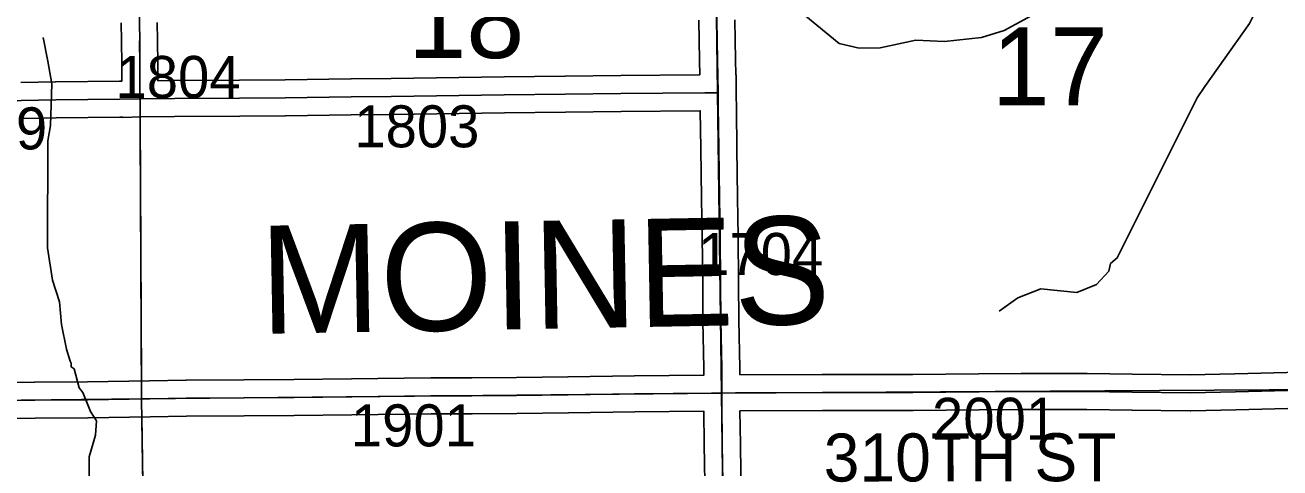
# Model space of a CAD drawing. Extents: x 23.6 to 68.7, y -63 to -29.
# Drawn here: x 38.618 to 40.707, y -54.804 to -54.066 of the extents above; entities that cross this region are included whole.
import ezdxf

# ---------------------------------------------------------------- set-up
doc = ezdxf.new("R2010")
doc.units = 0
for name, color, linetype in [('tdCoHydroRiver', 7, 'Continuous'), ('tdCoSecRdNmbr', 7, 'Continuous'), ('tdCoSecRdTxt', 7, 'Continuous'), ('tdCoSecRteBand', 7, 'Continuous'), ('tdCoSecRteCL', 7, 'Continuous'), ('tdCoSectLine', 7, 'Continuous'), ('tdCoSectLinePart', 7, 'Continuous'), ('tdCoSectNmbr', 7, 'Continuous'), ('tdCoSurfAsphalt', 7, 'Continuous'), ('tdCoSurfGravel', 7, 'Continuous'), ('tdCoTwpBndry', 7, 'Continuous'), ('tdCoTwpBndryShd', 7, 'Continuous'), ('tdCoTwpNameTxt', 7, 'Continuous')]:
    doc.layers.add(name, color=color, linetype=linetype)

msp = doc.modelspace()

# ---------------------------------------------------------------- linework, layer by layer
at = {"layer": 'tdCoHydroRiver'}
for points in [[(40.7641, -53.759), (40.6872, -53.7992), (40.6525, -53.8043), (40.6098, -53.7952), (40.5829, -53.7923), (40.5704, -53.8003), (40.4953, -53.8768), (40.4265, -53.9485), (40.3748, -53.9821), (40.3467, -54.0187), (40.3059, -54.0428), (40.2478, -54.0749), (40.21, -54.0863), (40.1485, -54.0932), (40.1011, -54.0905), (40.0413, -54.1037), (40.0065, -54.104), (39.9733, -54.0965), (39.9144, -54.0481), (39.9049, -54.0434), (39.8796, -54.0405), (39.8639, -54.0454)], [(41, -53.8247), (40.9937, -53.8279), (40.98, -53.8801), (40.966, -53.9007), (40.9424, -53.912), (40.9202, -53.9043), (40.9012, -53.9029), (40.8417, -53.9446), (40.7741, -53.9784), (40.7158, -53.9915), (40.6796, -54.0045), (40.6687, -54.0172), (40.6658, -54.0441), (40.6565, -54.0631), (40.5817, -54.168), (40.5693, -54.1871), (40.4361, -54.4536), (40.4251, -54.4631), (40.4221, -54.4758), (40.4018, -54.4981), (40.3687, -54.511), (40.3087, -54.5053), (40.2709, -54.5199), (40.2396, -54.5423)], [(38.7382, -55.107), (38.734, -54.9807), (38.7307, -54.965), (38.7254, -54.8893), (38.7245, -54.7851), (38.7353, -54.7487), (38.7367, -54.725), (38.7271, -54.7093), (38.7142, -54.6778), (38.7078, -54.67), (38.6997, -54.6385), (38.6949, -54.6353), (38.6948, -54.629), (38.6932, -54.6259), (38.6868, -54.6054), (38.6785, -54.5644), (38.6751, -54.5266), (38.6637, -54.4904), (38.6554, -54.4368), (38.6556, -54.2584), (38.6601, -54.2331), (38.6627, -54.1636), (38.6561, -54.1258), (38.6479, -54.0864)]]:
    msp.add_lwpolyline(points, dxfattribs=at)
at = {"layer": 'tdCoSecRteBand'}
for points in [[(38.838, -54.0612), (38.8384, -54.0912), (38.839, -54.1302), (38.839, -54.1303), (38.839, -54.1304), (38.8392, -54.1583), (38.8394, -54.1583), (38.8394, -54.1584), (38.8663, -54.1582), (38.975, -54.1572), (38.975, -54.1572), (38.9751, -54.1572), (39.0507, -54.1569), (39.1602, -54.1552), (39.1603, -54.1552), (39.1603, -54.1552), (39.2272, -54.1544), (39.4154, -54.1521), (39.5168, -54.1506), (39.5169, -54.1506), (39.517, -54.1506), (39.6097, -54.1498), (39.7412, -54.1484), (39.7408, -54.1245), (39.7408, -54.1245), (39.7408, -54.1245), (39.7398, -54.0576)], [(39.7998, -54.0567), (39.8008, -54.1235), (39.8012, -54.1479), (39.8012, -54.1483), (39.8016, -54.1483), (39.8016, -54.1781), (39.8021, -54.2078), (39.8021, -54.2078), (39.803, -54.2706), (39.803, -54.2706), (39.803, -54.2706), (39.804, -54.3537), (39.805, -54.418), (39.805, -54.418), (39.805, -54.4181), (39.8059, -54.4933), (39.8059, -54.4934), (39.8059, -54.4934), (39.8064, -54.5579), (39.8079, -54.6366), (39.8079, -54.6369), (39.8079, -54.6372), (39.8079, -54.6486)], [(38.611, -54.1612), (38.6689, -54.1602), (38.669, -54.1602), (38.6691, -54.1602), (38.7753, -54.1589), (38.7754, -54.1589), (38.7754, -54.1589), (38.7792, -54.1589), (38.779, -54.1309), (38.7784, -54.092), (38.7781, -54.062)], [(38.5547, -54.662), (38.6337, -54.6607), (38.6339, -54.6606), (38.634, -54.6606), (38.7221, -54.66), (38.8252, -54.6582), (38.8252, -54.6582), (38.8253, -54.6582), (38.8858, -54.6573), (38.886, -54.6573), (38.8861, -54.6573), (38.9823, -54.6569), (39.0655, -54.656), (39.1614, -54.6549), (39.1614, -54.6549), (39.1614, -54.6549), (39.2934, -54.6536), (39.2935, -54.6536), (39.2936, -54.6536), (39.3616, -54.6534), (39.4359, -54.6528), (39.5218, -54.6515), (39.5218, -54.6515), (39.5219, -54.6515), (39.6323, -54.6501), (39.6324, -54.6501), (39.6324, -54.6501), (39.7479, -54.6492), (39.7479, -54.6489), (39.7479, -54.6375), (39.7464, -54.5588), (39.7464, -54.5587), (39.7464, -54.5585), (39.746, -54.494), (39.745, -54.4189), (39.744, -54.3546), (39.744, -54.3545), (39.744, -54.3544), (39.743, -54.2714), (39.7421, -54.2084), (39.6103, -54.2098), (39.6103, -54.2098), (39.6103, -54.2098), (39.5176, -54.2106), (39.4163, -54.2121), (39.4162, -54.2121), (39.4162, -54.2121), (39.228, -54.2144), (39.1611, -54.2152), (39.0515, -54.2169), (39.0513, -54.2169), (39.0512, -54.2169), (38.9754, -54.2172), (38.8668, -54.2182), (38.8667, -54.2182), (38.8667, -54.2182), (38.8102, -54.2186), (38.7806, -54.2194), (38.7806, -54.2189), (38.776, -54.2189), (38.6699, -54.2202), (38.6119, -54.2212)], [(39.8079, -54.6486), (39.9452, -54.648), (39.9452, -54.648), (39.9452, -54.648), (40.0958, -54.6477), (40.2058, -54.6465), (40.2058, -54.6465), (40.2059, -54.6465), (40.2764, -54.646), (40.2765, -54.646), (40.2766, -54.646), (40.3855, -54.646), (40.3858, -54.646), (40.386, -54.646), (40.4613, -54.6471), (40.5577, -54.6483), (40.6321, -54.6465), (40.6321, -54.6465), (40.6321, -54.6465), (40.7402, -54.6441)], [(40.7416, -54.7041), (40.6335, -54.7065), (40.5586, -54.7083), (40.5581, -54.7083), (40.5575, -54.7083), (40.4605, -54.7071), (40.4605, -54.7071), (40.4605, -54.7071), (40.3853, -54.706), (40.2767, -54.706), (40.2064, -54.7065), (40.0963, -54.7077), (40.0962, -54.7077), (40.096, -54.7077), (39.9454, -54.708), (39.8081, -54.7086), (39.8087, -54.7641), (39.8099, -54.858)], [(39.7499, -54.8587), (39.7487, -54.7648), (39.7487, -54.7648), (39.7487, -54.7648), (39.7481, -54.7092), (39.633, -54.7101), (39.5227, -54.7115), (39.4367, -54.7128), (39.4366, -54.7128), (39.4365, -54.7128), (39.362, -54.7134), (39.3619, -54.7134), (39.3618, -54.7134), (39.2939, -54.7136), (39.162, -54.7149), (39.0662, -54.716), (39.0662, -54.716), (39.0662, -54.716), (38.9829, -54.7169), (38.9828, -54.7169), (38.9827, -54.7169), (38.8866, -54.7173), (38.8262, -54.7182), (38.723, -54.72), (38.7229, -54.72), (38.7227, -54.72), (38.6346, -54.7206), (38.5556, -54.722)]]:
    msp.add_lwpolyline(points, dxfattribs=at)
at = {"layer": 'tdCoSecRteCL'}
for points in [[(39.7716, -54.1783), (39.7708, -54.124), (39.7698, -54.0572), (39.769, -54.0042), (39.7681, -53.9553), (39.7678, -53.9107), (39.7668, -53.8416), (39.7661, -53.783), (39.7653, -53.7373), (39.7644, -53.6611), (39.7629, -53.5519), (39.7616, -53.468), (39.7609, -53.4015), (39.7599, -53.3243), (39.7584, -53.2333), (39.7577, -53.1752)], [(38.8097, -54.1886), (38.8093, -54.1728), (38.809, -54.1306), (38.8084, -54.0916)], [(38.8097, -54.1886), (38.8098, -54.1886), (38.8665, -54.1882), (38.9752, -54.1872), (39.051, -54.1869), (39.1607, -54.1852), (39.2276, -54.1844), (39.4158, -54.1821), (39.5173, -54.1806), (39.61, -54.1798), (39.7494, -54.1783), (39.7716, -54.1783)], [(39.7779, -54.6789), (39.7779, -54.6372), (39.7764, -54.5583), (39.7759, -54.4937), (39.775, -54.4185), (39.774, -54.3541), (39.773, -54.271), (39.772, -54.2007), (39.7716, -54.1783)], [(38.3054, -54.1933), (38.4353, -54.1935), (38.4761, -54.193), (38.6114, -54.1912), (38.6694, -54.1902), (38.7757, -54.1889), (38.8097, -54.1886)], [(37.81, -54.6998), (37.9437, -54.6985), (38.0909, -54.6974), (38.2411, -54.6953), (38.4222, -54.6932), (38.5551, -54.692), (38.6342, -54.6906), (38.7225, -54.69), (38.8257, -54.6882), (38.8863, -54.6873), (38.9826, -54.6869), (39.0659, -54.686), (39.1617, -54.6849), (39.2937, -54.6836), (39.3618, -54.6834), (39.4362, -54.6828), (39.5222, -54.6815), (39.6327, -54.6801), (39.7607, -54.679), (39.7779, -54.6789)], [(39.7779, -54.6789), (39.8005, -54.6786), (39.9453, -54.678), (40.096, -54.6777), (40.2061, -54.6765), (40.2766, -54.676), (40.3855, -54.676), (40.4609, -54.6771), (40.5579, -54.6783), (40.6328, -54.6765), (40.741, -54.6741), (40.7803, -54.6731)], [(39.7867, -55.4585), (39.7863, -55.4318), (39.7853, -55.3164), (39.7833, -55.1903), (39.7824, -55.066), (39.7809, -54.9736), (39.7799, -54.8584), (39.7787, -54.7644), (39.7779, -54.6949), (39.7779, -54.6789)]]:
    msp.add_lwpolyline(points, dxfattribs=at)
at = {"layer": 'tdCoSectLine'}
for points in [[(39.7642, -53.6757), (39.7776, -54.6788)], [(38.8068, -53.6871), (38.8119, -54.6885)], [(38.8119, -54.6885), (39.7776, -54.6788)], [(39.7776, -54.6788), (40.78, -54.6731)], [(39.7776, -54.6788), (39.79, -55.6803)], [(37.8096, -54.6998), (38.8119, -54.6885)], [(38.8119, -54.6885), (38.8276, -55.6912)]]:
    msp.add_lwpolyline(points, dxfattribs=at)
at = {"layer": 'tdCoSectLinePart'}
for points in [[(38.8095, -54.2191), (38.8118, -54.6583)], [(38.8124, -54.7183), (38.8276, -55.6912)]]:
    msp.add_lwpolyline(points, dxfattribs=at)
at = {"layer": 'tdCoSurfAsphalt'}
for points in [[(39.7779, -54.6789), (39.7779, -54.6372), (39.7764, -54.5583), (39.7759, -54.4937), (39.775, -54.4185), (39.774, -54.3541), (39.773, -54.271), (39.772, -54.2007), (39.7716, -54.1783), (39.7708, -54.124), (39.7698, -54.0572)], [(38.5551, -54.692), (38.6342, -54.6906), (38.7225, -54.69), (38.8257, -54.6882), (38.8863, -54.6873), (38.9826, -54.6869), (39.0659, -54.686), (39.1617, -54.6849), (39.2937, -54.6836), (39.3618, -54.6834), (39.4362, -54.6828), (39.5222, -54.6815), (39.6327, -54.6801), (39.7607, -54.679), (39.7779, -54.6789)], [(39.7779, -54.6789), (39.8005, -54.6786), (39.9453, -54.678), (40.096, -54.6777), (40.2061, -54.6765), (40.2766, -54.676), (40.3855, -54.676), (40.4609, -54.6771), (40.5579, -54.6783), (40.6328, -54.6765), (40.741, -54.6741)]]:
    msp.add_lwpolyline(points, dxfattribs=at)
at = {"layer": 'tdCoSurfGravel'}
for points in [[(38.8097, -54.1886), (38.8093, -54.1728), (38.809, -54.1306), (38.8084, -54.0916)], [(38.8098, -54.1886), (38.8665, -54.1882), (38.9752, -54.1872), (39.051, -54.1869), (39.1607, -54.1852), (39.2276, -54.1844), (39.4158, -54.1821), (39.5173, -54.1806), (39.61, -54.1798), (39.7494, -54.1783), (39.7716, -54.1783)], [(38.3054, -54.1933), (38.4353, -54.1935), (38.4761, -54.193), (38.6114, -54.1912), (38.6694, -54.1902), (38.7757, -54.1889), (38.8097, -54.1886), (38.8098, -54.1886)], [(39.7799, -54.8584), (39.7787, -54.7644), (39.7779, -54.6949), (39.7779, -54.6789)]]:
    msp.add_lwpolyline(points, dxfattribs=at)
at = {"layer": 'tdCoTwpBndry'}
for points in [[(38.8118, -54.6584), (38.8095, -54.2188)], [(38.8303, -55.9312), (38.8276, -55.6912), (38.8124, -54.7185)]]:
    msp.add_lwpolyline(points, dxfattribs=at)
at = {"layer": 'tdCoTwpBndryShd'}
msp.add_lwpolyline([(38.629, -40.6849), (38.6311, -41.6817), (38.6617, -42.6826), (38.6662, -43.6771), (38.6815, -44.677), (38.6948, -45.6802), (38.7111, -46.6468), (38.7223, -47.6479), (38.7331, -48.6502), (38.7634, -49.6525), (38.7727, -50.6504), (38.7816, -51.657), (38.7858, -52.6972), (38.8068, -53.6871), (38.8119, -54.6885), (38.8276, -55.6912), (38.8374, -56.6904), (38.8607, -57.6881)], dxfattribs=at)

# ---------------------------------------------------------------- texts
at = {"layer": 'tdCoSecRdNmbr'}
for s, rotation, p in [('1804', 0.0304, (38.7685, -54.1871)), ('1309', 0.0302, (38.4466, -54.2728)), ('1803', 0.0307, (39.1661, -54.2694)), ('1704', 0.0311, (39.7384, -54.4821)), ('2001', 0.0314, (40.1278, -54.7567)), ('1901', 0.0307, (39.1603, -54.7677))]:
    msp.add_text(s, height=0.07, rotation=rotation, dxfattribs=at).set_placement(p)
at = {"layer": 'tdCoSecRdTxt'}
msp.add_text('310TH ST', height=0.08, rotation=0.0745, dxfattribs=at).set_placement((39.9475, -54.8263))
at = {"layer": 'tdCoSectNmbr'}
for s, rotation, p in [('18', 0.0307, (39.2558, -54.1206)), ('17', 0.0315, (40.2274, -54.1996))]:
    msp.add_text(s, height=0.13, rotation=rotation, dxfattribs=at).set_placement(p)
at = {"layer": 'tdCoTwpNameTxt'}
msp.add_text('MOINES', height=0.18, rotation=1.0313, dxfattribs=at).set_placement((39.0102, -54.5802))

doc.saveas('drawing.dxf')
